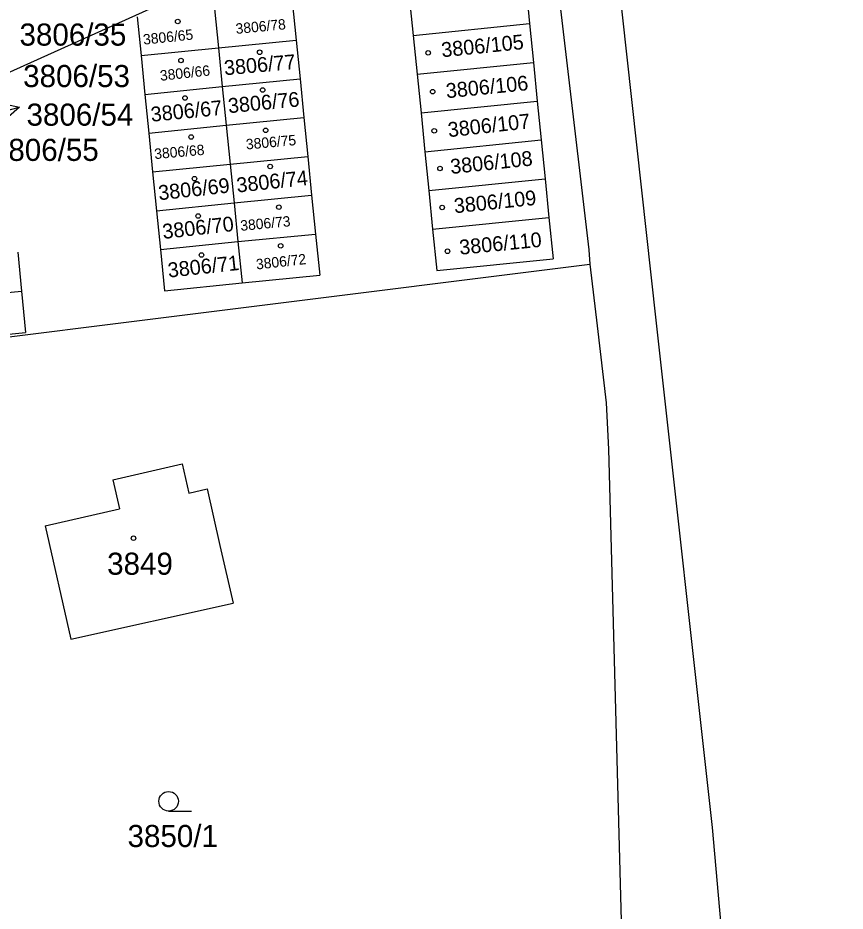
# Model space of a CAD drawing. Extents: x -735092 to -733385, y -1122435 to -1118992.
# Drawn here: x -734192.6 to -734129, y -1121325.7 to -1121257 of the extents above; entities that cross this region are included whole.
import ezdxf

# ---------------------------------------------------------------- set-up
doc = ezdxf.new("R2010")
doc.units = 0
for name, color, linetype in [('Vrstva 1', 7, 'Continuous'), ('Vrstva 12', 7, 'Continuous'), ('Vrstva 16', 7, 'Continuous'), ('Vrstva 18', 7, 'Continuous'), ('Vrstva 19', 7, 'Continuous'), ('Vrstva 25', 7, 'Continuous')]:
    doc.layers.add(name, color=color, linetype=linetype)

msp = doc.modelspace()

# ---------------------------------------------------------------- linework, layer by layer
at = {"layer": 'Vrstva 1'}
for points in [[(-734159.13, -1121185.95), (-734148.68, -1121274.85)], [(-734153.58, -1121189.07), (-734143.54, -1121280.27)], [(-734153.54, -1121254.47), (-734153.24, -1121257.45)], [(-734162.49, -1121255.37), (-734162.19, -1121258.35)], [(-734171.49, -1121255.73), (-734171.19, -1121258.71)], [(-734177.46, -1121256.32), (-734177.16, -1121259.3)], [(-734183.42, -1121256.92), (-734183.12, -1121259.9)], [(-734162.19, -1121258.35), (-734153.24, -1121257.45)], [(-734153.24, -1121257.45), (-734152.94, -1121260.44)], [(-734177.16, -1121259.3), (-734171.19, -1121258.71)], [(-734171.19, -1121258.71), (-734170.89, -1121261.7)], [(-734162.19, -1121258.35), (-734161.89, -1121261.33)], [(-734183.12, -1121259.9), (-734177.16, -1121259.3)], [(-734177.16, -1121259.3), (-734176.87, -1121262.29)], [(-734183.12, -1121259.9), (-734182.83, -1121262.89)], [(-734161.89, -1121261.33), (-734152.94, -1121260.44)], [(-734152.94, -1121260.44), (-734152.65, -1121263.42)], [(-734176.87, -1121262.29), (-734170.89, -1121261.7)], [(-734170.89, -1121261.7), (-734170.6, -1121264.68)], [(-734161.89, -1121261.33), (-734161.59, -1121264.32)], [(-734182.83, -1121262.89), (-734176.87, -1121262.29)], [(-734176.87, -1121262.29), (-734176.57, -1121265.27)], [(-734182.83, -1121262.89), (-734182.53, -1121265.87)], [(-734161.59, -1121264.32), (-734152.65, -1121263.42)], [(-734152.65, -1121263.42), (-734152.35, -1121266.4)], [(-734161.59, -1121264.32), (-734161.29, -1121267.3)], [(-734176.57, -1121265.27), (-734170.6, -1121264.68)], [(-734170.6, -1121264.68), (-734170.3, -1121267.67)], [(-734182.53, -1121265.87), (-734176.57, -1121265.27)], [(-734176.57, -1121265.27), (-734176.27, -1121268.25)], [(-734182.53, -1121265.87), (-734182.23, -1121268.85)], [(-734161.29, -1121267.3), (-734152.35, -1121266.4)], [(-734152.35, -1121266.4), (-734152.05, -1121269.38)], [(-734176.27, -1121268.25), (-734170.3, -1121267.67)], [(-734170.3, -1121267.67), (-734170, -1121270.65)], [(-734161.29, -1121267.3), (-734160.99, -1121270.28)], [(-734182.23, -1121268.85), (-734176.27, -1121268.25)], [(-734176.27, -1121268.25), (-734175.97, -1121271.24)], [(-734182.23, -1121268.85), (-734181.93, -1121271.84)], [(-734160.99, -1121270.28), (-734152.05, -1121269.38)], [(-734152.05, -1121269.38), (-734151.75, -1121272.37)], [(-734160.99, -1121270.28), (-734160.7, -1121273.27)], [(-734181.93, -1121271.84), (-734175.97, -1121271.24)], [(-734175.97, -1121271.24), (-734170, -1121270.65)], [(-734175.97, -1121271.24), (-734175.67, -1121274.22)], [(-734170, -1121270.65), (-734169.7, -1121273.64)], [(-734181.93, -1121271.84), (-734181.63, -1121274.82)], [(-734160.7, -1121273.27), (-734151.75, -1121272.37)], [(-734151.75, -1121272.37), (-734151.43, -1121275.55)], [(-734160.7, -1121273.27), (-734160.38, -1121276.45)], [(-734175.67, -1121274.22), (-734169.7, -1121273.64)], [(-734169.7, -1121273.64), (-734169.38, -1121276.8)], [(-734181.63, -1121274.82), (-734175.67, -1121274.22)], [(-734175.67, -1121274.22), (-734175.35, -1121277.4)], [(-734192.61, -1121275.03), (-734192.32, -1121278.03)], [(-734181.63, -1121274.82), (-734181.31, -1121278)], [(-734148.68, -1121274.85), (-734148.61, -1121275.95)], [(-734229.36, -1121286.05), (-734148.61, -1121275.95)], [(-734160.38, -1121276.45), (-734151.43, -1121275.55)], [(-734148.61, -1121275.95), (-734148.04, -1121280.7)], [(-734175.35, -1121277.4), (-734169.38, -1121276.8)], [(-734181.31, -1121278), (-734175.35, -1121277.4)], [(-734201.39, -1121278.9), (-734192.32, -1121278.03)], [(-734192.32, -1121278.03), (-734192, -1121281.2)], [(-734148.04, -1121280.7), (-734147.34, -1121286.62)], [(-734143.54, -1121280.27), (-734139.19, -1121319.29)], [(-734201.11, -1121282.12), (-734192, -1121281.2)], [(-734147.34, -1121286.62), (-734147.18, -1121290.2)], [(-734147.18, -1121290.2), (-734145.94, -1121336.05)], [(-734185.29, -1121292.56), (-734179.96, -1121291.32)], [(-734179.96, -1121291.32), (-734179.45, -1121293.57)], [(-734185.29, -1121292.56), (-734184.79, -1121294.78)], [(-734179.45, -1121293.57), (-734178.04, -1121293.25)], [(-734178.04, -1121293.25), (-734177.05, -1121297.61)], [(-734190.5, -1121296.08), (-734184.79, -1121294.78)], [(-734190.5, -1121296.08), (-734188.52, -1121304.81)], [(-734177.05, -1121297.61), (-734176.04, -1121302.04)], [(-734188.52, -1121304.81), (-734176.04, -1121302.04)], [(-734139.19, -1121319.29), (-734137.71, -1121336.07)]]:
    msp.add_lwpolyline(points, dxfattribs=at)
at = {"layer": 'Vrstva 12'}
msp.add_lwpolyline([(-734230.19, -1121277.82), (-734098.32, -1121218.35)], dxfattribs=at)
at = {"layer": 'Vrstva 25'}
for points in [[(-734193.558, -1121263.639), (-734192.465, -1121263.874), (-734193.309, -1121264.607)], [(-734195.37, -1121264.62), (-734192.465, -1121263.874)], [(-734181, -1121318.03), (-734179.25, -1121318.03)]]:
    msp.add_lwpolyline(points, dxfattribs=at)
for centre, radius in [((-734180.3, -1121257.28), 0.175), ((-734174, -1121259.65), 0.175), ((-734161.04, -1121259.7), 0.175), ((-734180.05, -1121260.28), 0.175), ((-734173.77, -1121262.55), 0.175), ((-734179.74, -1121263.17), 0.175), ((-734160.69, -1121262.68), 0.175), ((-734173.54, -1121265.66), 0.175), ((-734160.57, -1121265.7), 0.175), ((-734179.27, -1121266.17), 0.175), ((-734173.19, -1121268.44), 0.175), ((-734160.13, -1121268.59), 0.175), ((-734179.01, -1121269.38), 0.175), ((-734172.52, -1121271.57), 0.175), ((-734159.96, -1121271.59), 0.175), ((-734178.73, -1121272.25), 0.175), ((-734172.38, -1121274.54), 0.175), ((-734178.47, -1121275.25), 0.175), ((-734159.55, -1121274.96), 0.175), ((-734183.7, -1121297.04), 0.175), ((-734181, -1121317.28), 0.75)]:
    msp.add_circle(centre, radius, dxfattribs=at)

# ---------------------------------------------------------------- texts
at = {"layer": 'Vrstva 16'}
for s, p in [('3806/35', (-734192.47, -1121259.14)), ('3806/53', (-734192.19, -1121262.33)), ('3806/54', (-734191.93, -1121265.3)), ('3806/55', (-734194.59, -1121268.01))]:
    msp.add_text(s, height=1.7, dxfattribs=at).set_placement(p)
at = {"layer": 'Vrstva 18'}
msp.add_text('3850/1', height=1.7, dxfattribs=at).set_placement((-734184.16, -1121320.8))
at = {"layer": 'Vrstva 19'}
for s, height, rotation, p in [('3806/78', 0.8, 5.40004, (-734175.81, -1121258.243)), ('3806/65', 0.8, 6.00005, (-734182.923, -1121259.071)), ('3806/105', 1.14, 5.80005, (-734159.972, -1121260.041)), ('3806/77', 1.14, 5.10004, (-734176.689, -1121261.424)), ('3806/66', 0.8, 6.20005, (-734181.623, -1121261.85)), ('3806/106', 1.14, 5.70004, (-734159.621, -1121263.192)), ('3806/76', 1.14, 5.50004, (-734176.381, -1121264.342)), ('3806/67', 1.14, 5.60004, (-734182.321, -1121265.002)), ('3806/107', 1.14, 6.30005, (-734159.464, -1121266.19)), ('3806/75', 0.8, 5.10004, (-734175.019, -1121267.134)), ('3806/68', 0.8, 5.00004, (-734182.069, -1121267.874)), ('3806/108', 1.14, 6.00005, (-734159.283, -1121269.021)), ('3806/74', 1.14, 6.20005, (-734175.723, -1121270.45)), ('3806/69', 1.14, 6.30005, (-734181.734, -1121271.04)), ('3806/109', 1.14, 5.90005, (-734159.002, -1121272.041)), ('3806/70', 1.14, 6.50005, (-734181.414, -1121274.019)), ('3806/73', 0.8, 5.30004, (-734175.45, -1121273.393)), ('3806/110', 1.14, 5.60004, (-734158.591, -1121275.232)), ('3806/71', 1.14, 6.20005, (-734181.003, -1121276.99)), ('3806/72', 0.8, 6.30005, (-734174.234, -1121276.37))]:
    msp.add_text(s, height=height, rotation=rotation, dxfattribs=at).set_placement(p)
msp.add_text('3849', height=1.7, dxfattribs=at).set_placement((-734185.73, -1121299.85))

doc.saveas('drawing.dxf')
